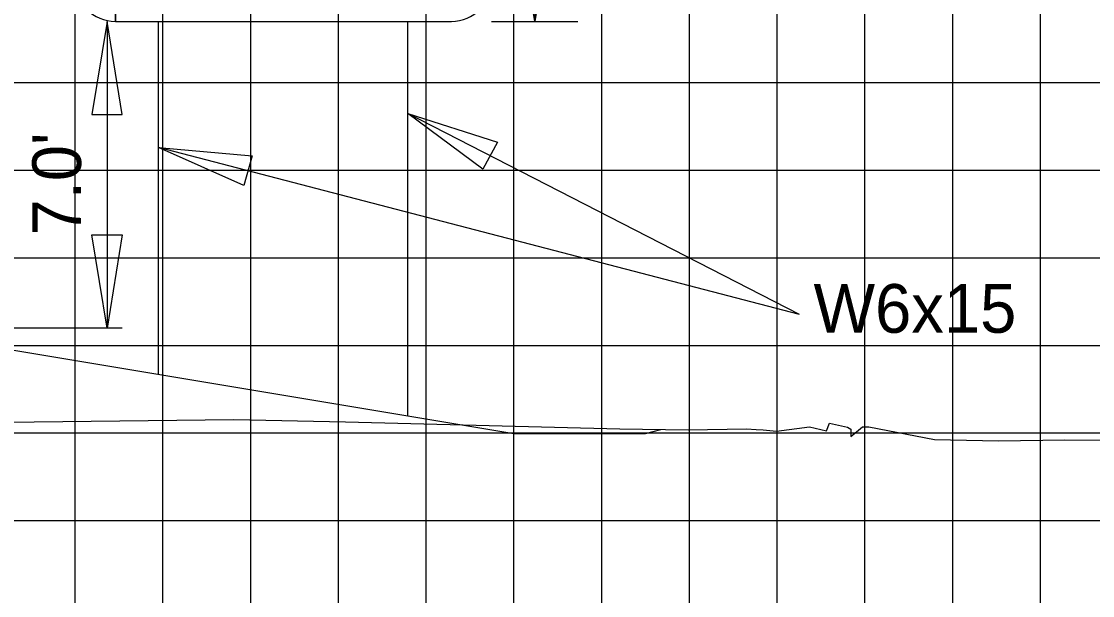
# Model space of a CAD drawing. Extents: x 2193008 to 2198143, y 1236112 to 1237864.
# Drawn here: x 2195279.56 to 2195303.97, y 1237266.4 to 1237279.5 of the extents above; entities that cross this region are included whole.
import ezdxf

# ---------------------------------------------------------------- set-up
doc = ezdxf.new("R2010")
doc.units = 0
for name, color, linetype in [('3', 7, 'Continuous'), ('60', 7, 'Continuous'), ('GSCOLORFILL', 7, 'Continuous'), ('GSDIMS', 7, 'Continuous'), ('Level 55', 7, 'Continuous'), ('M-ROADS', 7, 'Continuous')]:
    doc.layers.add(name, color=color, linetype=linetype)

msp = doc.modelspace()

# ---------------------------------------------------------------- linework, layer by layer
at = {"layer": '3'}
for q in [(2195288.366, 1237277.395), (2195282.683, 1237276.621)]:
    msp.add_line((2195297.29, 1237272.809), q, dxfattribs=at)
at = {"layer": '60'}
msp.add_lwpolyline([(2195238.783, 1237272.132), (2195240.287, 1237272.508), (2195244.287, 1237272.348), (2195244.617, 1237272.348), (2195244.783, 1237271.848), (2195246.783, 1237272.014), (2195252.783, 1237272.146), (2195268.783, 1237272.498), (2195276.783, 1237272.178), (2195278.783, 1237272.098), (2195290.783, 1237270.098), (2195293.783, 1237270.098), (2195294.132, 1237270.185)], dxfattribs=at)
at = {"layer": 'GSCOLORFILL'}
for p, q in [((2195281.699, 1237279.498), (2195281.699, 1237279.665)), ((2195281.701, 1237279.665), (2195281.701, 1237279.498)), ((2195281.701, 1237279.498), (2195289.358, 1237279.498))]:
    msp.add_line(p, q, dxfattribs=at)
for centre, start, end in [((2195281.699, 1237280.414), 180, 270), ((2195289.358, 1237280.414), 270, 0)]:
    msp.add_arc(centre, 0.916, start, end, dxfattribs=at)
at = {"layer": 'GSDIMS'}
for p, q in [((2195291.258, 1237286.5), (2195291.258, 1237279.498)), ((2195281.507, 1237279.498), (2195281.507, 1237272.498)), ((2195282.683, 1237271.448), (2195282.683, 1237279.498)), ((2195288.366, 1237270.501), (2195288.366, 1237279.498)), ((2195290.274, 1237279.498), (2195292.242, 1237279.498)), ((2195281.854, 1237272.498), (2195268.783, 1237272.498))]:
    msp.add_line(p, q, dxfattribs=at)
for points in [[(2195291.258, 1237279.498), (2195290.911, 1237281.627), (2195291.605, 1237281.627)], [(2195281.507, 1237279.498), (2195281.16, 1237277.37), (2195281.854, 1237277.37)], [(2195288.366, 1237277.395), (2195290.405, 1237276.742), (2195290.07, 1237276.124)], [(2195282.683, 1237276.621), (2195284.816, 1237276.427), (2195284.624, 1237275.751)], [(2195281.507, 1237272.498), (2195281.16, 1237274.627), (2195281.854, 1237274.627)]]:
    msp.add_lwpolyline(points, close=True, dxfattribs=at)
at = {"layer": 'M-ROADS'}
for p, q in [((2195280.783, 1237258.106), (2195280.783, 1237318.106)), ((2195282.783, 1237258.106), (2195282.783, 1237318.106)), ((2195284.783, 1237258.106), (2195284.783, 1237318.106)), ((2195286.783, 1237258.106), (2195286.783, 1237318.106)), ((2195288.783, 1237258.106), (2195288.783, 1237318.106)), ((2195290.783, 1237258.106), (2195290.783, 1237318.106)), ((2195292.783, 1237258.106), (2195292.783, 1237318.106)), ((2195294.783, 1237258.106), (2195294.783, 1237318.106)), ((2195296.783, 1237258.106), (2195296.783, 1237318.106)), ((2195298.783, 1237258.106), (2195298.783, 1237318.106)), ((2195300.783, 1237258.106), (2195300.783, 1237318.106)), ((2195302.783, 1237258.106), (2195302.783, 1237318.106)), ((2195238.783, 1237278.106), (2195368.783, 1237278.106)), ((2195238.783, 1237276.106), (2195368.783, 1237276.106)), ((2195238.783, 1237274.106), (2195368.783, 1237274.106)), ((2195238.783, 1237272.106), (2195368.783, 1237272.106)), ((2195238.783, 1237270.106), (2195368.783, 1237270.106)), ((2195238.783, 1237268.106), (2195368.783, 1237268.106))]:
    msp.add_line(p, q, dxfattribs=at)
msp.add_lwpolyline([(2195275.943, 1237270.317), (2195284.398, 1237270.412), (2195286.945, 1237270.359), (2195293.199, 1237270.2), (2195294.757, 1237270.175), (2195296.086, 1237270.201), (2195296.301, 1237270.188), (2195296.46, 1237270.179), (2195296.77, 1237270.151), (2195297.521, 1237270.246), (2195297.908, 1237270.152), (2195297.976, 1237270.328), (2195298.384, 1237270.24), (2195298.458, 1237270.193), (2195298.458, 1237270.024), (2195298.728, 1237270.245), (2195298.873, 1237270.243), (2195300.366, 1237269.956), (2195301.826, 1237269.93), (2195303.34, 1237269.948), (2195304.187, 1237269.939)], dxfattribs=at)

# ---------------------------------------------------------------- texts
at = {"layer": 'Level 55'}
msp.add_text("7.0'", height=1.1105, rotation=90, dxfattribs=at).set_placement((2195280.914, 1237274.614))
msp.add_text('W6x15', height=1.1105, dxfattribs=at).set_placement((2195297.612, 1237272.393))

doc.saveas('drawing.dxf')
